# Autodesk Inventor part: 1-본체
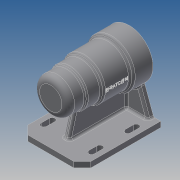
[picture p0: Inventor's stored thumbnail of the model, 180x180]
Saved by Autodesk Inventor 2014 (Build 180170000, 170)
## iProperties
Created: 2017-09
Part Number: 1-본체
Material: Generic
Document SubType Name: Modeling
Designer: kb542-27
Density: 1 g/cm^3
Appearance: Default
Author: kb542-27
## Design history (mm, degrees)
sketch "스케치1"
  geometry: L1 (-56, 0)-(56, 0); L2 (-50, 0)-(-56, 0); L3 (-56, 0)-(-56, 25); L4 (-56, 25)-(-31, 25); L5 (-31, 25)-(-31, 27); L6 (-31, 27)-(-11, 27); L7 (-11, 27)-(-11, 30); L8 (-11, 30)-(28, 30); L9 (28, 30)-(28, 34); L10 (28, 34)-(56, 34); L11 (56, 34)-(56, 21); L12 (56, 21)-(41, 21); L13 (41, 21)-(41, 24); L14 (41, 24)-(-13, 24); L15 (-13, 24)-(-13, 21); L16 (-13, 21)-(-25, 21); L17 (-25, 21)-(-25, 17.5); L18 (-25, 17.5)-(-43, 17.5); L19 (-43, 17.5)-(-43, 16); L20 (-43, 16)-(-47, 16); L21 (-47, 16)-(-47, 10.5); L22 (-47, 10.5)-(-50, 10.5); L23 (-50, 10.5)-(-50, 0); 2 further points
  constraints: 46 end point, 11 parallel, 10 perpendicular, 2 coincident, 2 collinear, 1 horizontal, 1 midpoint, 1 vertical alignment
  dimensions: "d0" = 112 distance between parallel lines of L11 L3; "d1" = 84 distance between parallel lines of L3 L9; "d2" = 45 distance between parallel lines of L3 L7; "d3" = 25 distance between parallel lines of L3 L5; "d4" = 42 diameter of L12 L1; "d5" = 48 diameter of L14 L1; "d6" = 42 diameter of L16 L1; "d7" = 35 diameter of L18 L1; "d8" = 32 diameter of L20 L1; "d9" = 21 diameter of L22 L1; "d10" = 3 distance of L21.end L22.end; "d11" = 4 distance of L19.end L20.end; "d12" = 18 distance of L17.end L18.end; "d13" = 12 distance of L15.end L16.end; "d14" = 54 distance of L13.end L14.end; "d15" = 15 distance of L11.end L12.end; "d16" = 60 diameter of L8 L1; "d17" = 54 diameter of L6 L1; "d18" = 50 diameter of L4 L1; "d19" = 68 diameter of L10 L1
revolve "회전1" sketch "스케치1" stored, may be unused: angle "d20" = 90 deg
node "작업 평면1"
sketch "스케치2"
  geometry: L1 (-56, 34)-(-56, -34) reference; L2 (-56, 45)-(44, 45); L3 (56, 33)-(56, -33); L4 (44, -45)-(-56, -45); L5 (-56, -45)-(-56, 45); L6 (56, 33)-(44, 45); L7 (56, -33)-(44, -45); L8 (-32, 34)-(-20, 34); L9 (-32, 30)-(-20, 30); L10 (-20, 38)-(-32, 38); L11 (20, 34)-(32, 34); L12 (20, 38)-(32, 38); L13 (32, 30)-(20, 30); L14 (0, 0)-(-56, 0); L15 (-32, -30)-(-20, -30); L16 (-20, -38)-(-32, -38); L17 (-32, -34)-(-20, -34); L18 (20, -34)-(32, -34); L19 (20, -38)-(32, -38); L20 (32, -30)-(20, -30); A1 r 4 centre (-32, 34) between (-32, 38) and (-32, 30); A2 r 4 centre (-20, 34) between (-20, 30) and (-20, 38); A3 r 4 centre (20, 34) between (20, 38) and (20, 30); A4 r 4 centre (32, 34) between (32, 30) and (32, 38); A5 r 4 centre (-20, -34) between (-20, -38) and (-20, -30); A6 r 4 centre (-32, -34) between (-32, -30) and (-32, -38); A7 r 4 centre (20, -34) between (20, -30) and (20, -38); A8 r 4 centre (32, -34) between (32, -38) and (32, -30); 6 further points
  constraints: 46 end point, 16 point on circle, 14 symmetric about line, 8 centre point, 8 tangent, 7 parallel, 4 midpoint, 4 point on line, 2 collinear, 1 horizontal, 1 horizontal alignment, 1 perpendicular, 4 other
  dimensions: "d22" = 112 distance of L2.start point (56, 45); "d23" = 90 distance of L4.end L2.start; "d24" = 12 distance of L3.start point (56, 45); "d25" = 12 distance of L2.end point (56, 45) (= d24); "d26" = 12 distance of L3.end point (56, -45) (= d24); "d27" = 12 distance of L4.start point (56, -45) (= d26); "d28" = 12 distance of L8.start L8.end; "d29" = 12 distance of L11.start L11.end; "d30" = 34 vertical distance of L14.start point (-26, 34); "d31" = 24 distance from line of L1 L8.start; "d33" = 4 radius of A2; "d34" = 4 radius of A4; "d35" = 40 distance of L11.start L8.end
extrude "돌출1" join sketch "스케치2" distance "d36" = 8; taper "d37" = 0 deg
sketch "스케치3"
  geometry: L1 (-62, 45)-(-62, -45) reference; L2 (-62, 35)-(-26.008, 21.9); L3 (-26.008, -21.9)-(-62, -35); L4 (-70, 45)-(-62, 45) reference; A1 r 34 centre (0, 0) between (-26.008, 21.9) and (-26.008, -21.9) reference
  constraints: 4 end point, 2 point on circle, 2 point on line
  dimensions: "d38" = 10 distance from line of L4 L2.start; "d39" = 10 distance of L1.end L3.end; "d40" = 110 deg angle of L1 L3; "d41" = 110 deg angle of L1 L2
extrude "돌출2" join sketch "스케치3" distance "d42" = 8; taper "d43" = 0 deg
sketch "스케치4"
  geometry: L1 (-56, -25)-(-56, 25) reference; L2 (-56, 25)-(-31, 25) reference; L3 (-31, 25)-(-31, 27) reference; L4 (-31, 27)-(-11, 27) reference; L5 (-11, 27)-(-11, 30) reference; L6 (-11, 30)-(28, 30) reference; L7 (28, 30)-(28, 34) reference; L8 (28, 34)-(56, 34) reference; L9 (56, 34)-(56, 21) reference; L10 (56, 21)-(41, 21) reference; L11 (41, 21)-(41, 24) reference; L12 (41, 24)-(-13, 24) reference; L13 (-13, 24)-(-13, 21) reference; L14 (-13, 21)-(-25, 21) reference; L15 (-25, 21)-(-25, 17.5) reference; L16 (-25, 17.5)-(-43, 17.5) reference; L17 (-43, 17.5)-(-43, 16) reference; L18 (-43, 16)-(-47, 16) reference; L19 (-47, 16)-(-47, 10.5) reference; L20 (-47, 10.5)-(-50, 10.5) reference; L21 (-50, 10.5)-(-50, -10.5) reference; L22 (-50, -10.5)-(-47, -10.5) reference; L23 (-47, -10.5)-(-47, -16) reference; L24 (-47, -16)-(-43, -16) reference; L25 (-43, -16)-(-43, -17.5) reference; L26 (-43, -17.5)-(-25, -17.5) reference; L27 (-25, -17.5)-(-25, -21) reference; L28 (-25, -21)-(-13, -21) reference; L29 (-13, -21)-(-13, -24) reference; L30 (-13, -24)-(41, -24) reference; L31 (41, -24)-(41, -21) reference; L32 (41, -21)-(56, -21) reference; L33 (56, -21)-(56, -70) reference; L34 (56, -70)-(-56, -70) reference; L35 (-56, -70)-(-56, -62) reference; L36 (-56, -62)-(48, -62) reference; L37 (48, -62)-(48, -34) reference; L38 (48, -34)-(28, -34) reference; L39 (28, -34)-(28, -30) reference; L40 (28, -30)-(-11, -30) reference; L41 (-11, -30)-(-11, -27) reference; L42 (-11, -27)-(-31, -27) reference; L43 (-31, -27)-(-31, -25) reference; L44 (-31, -25)-(-56, -25) reference; L45 (-24.622, -27)-(-34, -62); 1 further point
  constraints: 2 end point, 2 point on line
  dimensions: "d44" = 22 distance from line of L35 L45.end; "d45" = 105 deg angle of L36 L45
feature "리브1" sketch "스케치4" dims "d46" = 1, "d47" = 8, "d48" = 0, "d49" = 0, "d50" = 1, "d51" = 1
node "작업 평면3"
  node "작업 평면2"
sketch "스케치5"
  geometry: L1 (47.5, -26.008)-(47.5, 34) reference; 2 further points
  constraints: 1 horizontal alignment, 1 other
  dimensions: "d53" = 48 distance from line of L1 point (-0.5, 0)
feature "엠보싱1" sketch "스케치5" dims "d0" = 112, "d1" = 84, "d2" = 45, "d3" = 25, "d4" = 42, "d5" = 48, "d6" = 42, "d7" = 35, "d8" = 32, "d9" = 21, "d10" = 3, "d11" = 4, "d12" = 18, "d13" = 12, "d14" = 54, "d15" = 15, "d16" = 60, "d17" = 54, "d18" = 50, "d19" = 68, "d54" = 0.5, "d55" = 0
sketch "스케치6" dims "d56" = 52
  geometry: C1 r 21 at (70, 45) reference; A1 r 34 centre (70, 45) between (43.992, 23.1) and (43.992, 66.9) reference; 2 further points
  constraints: 2 horizontal alignment, 1 coincident, 2 other
hole "구멍1" sketch "스케치6" at (96, 45) diameter "d57" = 3.242; stored, may be unused: countersink angle "d61" = 90 deg, drill point angle "d63" = 118 deg; dims "d58" = 8, "d59" = 4, "d60" = 2, "d62" = 11
fillet "모깎기1" dims "d67" = 3, "d68" = 0.3
fillet "모깎기2" dims "d69" = 9
fillet "모깎기3" dims "d70" = 3
fillet "모깎기4" dims "d71" = 3
fillet "모깎기5" dims "d72" = 3
fillet "모깎기6" dims "d73" = 3
fillet "모깎기7" dims "d74" = 3
fillet "모깎기8" dims "d75" = 3
chamfer "모따기1" distance "d76" = 1; stored, may be unused: second distance "d77" = 2, angle "d78" = 45 deg
node "솔리드1"
pattern_circular "원형 패턴1" dims angle "d65" = 360 deg
node "절단 모서리 투영1"
other parameters: "d52" = 0.5
